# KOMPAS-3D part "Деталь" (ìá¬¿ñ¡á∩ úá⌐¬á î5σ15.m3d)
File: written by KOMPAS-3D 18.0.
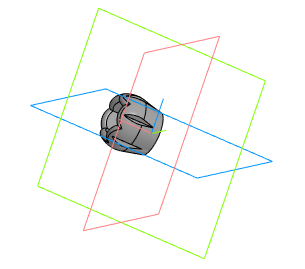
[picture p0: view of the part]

Document properties: Автор: Пользователь Windows; Полное имя файла: F:\Модели\Мех детали\Велосипед\Крепление фонаря\2\Накидная гайка М5х15.m3d

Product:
- Part/product: Деталь
    Масса: 0.00936817

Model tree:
1. Эскиз:1
2. Элемент вращения:1
     Угол 1 = 360
3. Эскиз:2  (with: Элемент вращения:1)
4. Элемент выдавливания:1
     Расстояние 1 = 15
5. Скругление:1  (with: Элемент вращения:1)
     Радиус = 1
6. Эскиз:3
7. Элемент выдавливания:2
     Расстояние 1 = 30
